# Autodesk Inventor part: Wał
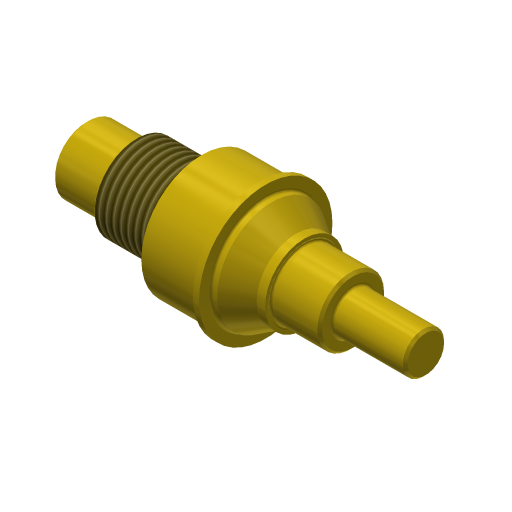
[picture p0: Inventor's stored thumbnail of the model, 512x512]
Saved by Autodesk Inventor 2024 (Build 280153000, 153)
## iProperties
Company: ATC
CustomPartVersion: 1
Created: 2023-03
Part Number: Wał
Material: Stal kuta
Document SubType Name: Modeling
Designer: Andrzej Jaskulski
Density: 1 g/cm^3
Appearance: Lśniąca — złota
Checked By: A.J.
Engr Approved By: Andrzej Jaskulski
Mfg Approved By: Andrzej Jaskulski
Authority: A.J.
Title: A.J.: Kurs R2024-MEP
Author: Andrzej Jaskulski
Revision Number: 1/24
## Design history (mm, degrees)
sketch "Szkic główny"
  geometry: L1 (0, 0)-(280, 0) reference; L2 (0, 0)-(0, 27.5); L3 (0, 27.5)-(40, 27.5); L4 (40, 27.5)-(40, 35); L5 (90, 35)-(90, 32.5); L6 (40, 35)-(90, 35); L7 (90, 32.5)-(95, 32.5); L8 (95, 32.5)-(95, 50); L9 (95, 50)-(143, 50); L10 (143, 50)-(143, 55); L11 (148, 55)-(148, 45); L12 (143, 55)-(148, 55); L13 (148, 45)-(153, 45); L14 (153, 45)-(173, 32.5); L15 (180, 32.5)-(180, 27.5); L16 (173, 32.5)-(180, 32.5); L17 (220, 27.5)-(220, 17); L18 (180, 27.5)-(220, 27.5); L19 (280, 17)-(280, 0); L20 (220, 17)-(280, 17)
  constraints: 40 end point, 9 vertical, 5 horizontal
  dimensions: "d14" = 70 diameter of L6 L1 (derived); "d15" = 65 diameter of L7 L1 (derived); "d16" = 110 diameter of L12 L1 (derived); "d17" = 90 diameter of L13 L1 (derived); "d18" = 65 diameter of L16 L1 (derived); "d19" = 34 diameter of L20 L1 (derived); "d45" = 55 diameter of L3 L1 (derived); "d46" = 100 diameter of L9 L1 (derived); "d47" = 55 diameter of L18 L1 (derived)
revolve "Obrót1" sketch "Szkic główny" stored, may be unused: angle "d6" = 0 deg
fillet "Zaokrąglenie7" dims "d48" = 2
chamfer "Faza3" distance "d20" = 2; stored, may be unused: second distance "d21" = 0.125, angle "d22" = 45 deg
chamfer "Faza4" distance "d24" = 2; stored, may be unused: second distance "d25" = 0.125, angle "d26" = 45 deg
node "Gwint2"
fillet "Zaokrąglenie8" dims "d49" = 0.5
node "Podcięcie3"
fillet "Zaokrąglenie3" dims "d32" = 0.5
chamfer "Faza6" distance "d34" = 0.5; stored, may be unused: second distance "d35" = 0.125, angle "d36" = 45 deg
fillet "Zaokrąglenie5" dims "d37" = 2
node "Podcięcie2"
chamfer "Faza7" distance "d38" = 2; stored, may be unused: second distance "d39" = 0.125, angle "d40" = 45 deg
fillet "Zaokrąglenie6" dims "d41" = 2
chamfer "Faza8" distance "d42" = 2; stored, may be unused: second distance "d43" = 0.125, angle "d44" = 45 deg
node "Bryła1"
node "Korpusy bryłowe"
node "Korpusy powierzchniowe"
feature "Gwint1" dims "d27" = 50, "d28" = 0
chamfer "Faza5" distance "d29" = 2; stored, may be unused: second distance "d30" = 2, angle "d31" = 45 deg
feature "iFeature1:2"
feature "iFeature1:3"
other parameters: "d0" = 0, "d1" = 0, "d2" = 0
